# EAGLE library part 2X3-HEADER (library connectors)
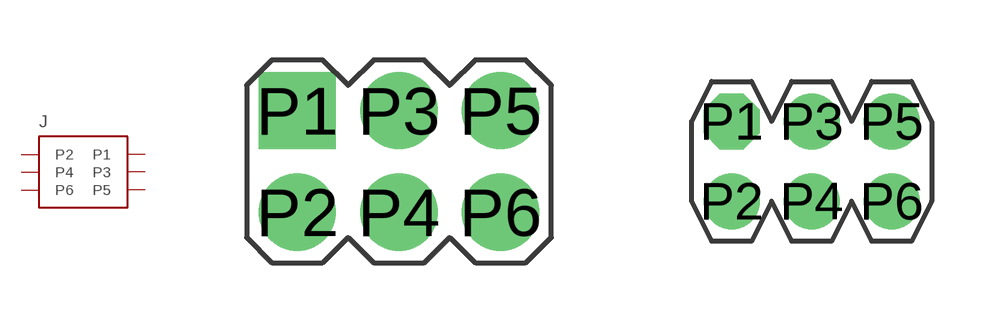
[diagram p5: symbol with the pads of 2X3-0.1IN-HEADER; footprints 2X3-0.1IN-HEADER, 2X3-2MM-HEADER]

Designator prefix J

## 2X3-HEADER0.1IN  [2X3-0.1IN-HEADER]
P1  P1  pas
P2  P2  pas
P3  P3  pas
P4  P4  pas
P5  P5  pas
P6  P6  pas

## 2X3-HEADER2MM  [2X3-2MM-HEADER]
Pads as for 2X3-0.1IN-HEADER

## 2X3-HEADERTYCO  [2X3-TYCO]
Pads as for 2X3-0.1IN-HEADER

## Footprint 2X3-0.1IN-HEADER (pad centres in mm)
drill 1.05 pad 1.93 square: P1 -2.54,1.27
drill 1.05 pad 1.93 round: P2 -2.54,-1.27; P3 0,1.27; P4 0,-1.27; P5 2.54,1.27; P6 2.54,-1.27

## Footprint 2X3-2MM-HEADER (pad centres in mm)
drill 0.85 pad 1.4 octagon: P1 -2,1
drill 0.85 pad 1.4 round: P2 -2,-1; P3 0,1; P4 0,-1; P5 2,1; P6 2,-1

## Footprint 2X3-TYCO (pad centres in mm)
drill 1.55 pad 3.2 square: P1 -4.953,4.572
drill 1.55 pad 3.2 round: P2 -4.953,-4.572; P3 0,4.572; P4 0,-4.572; P5 4.953,4.572; P6 4.953,-4.572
